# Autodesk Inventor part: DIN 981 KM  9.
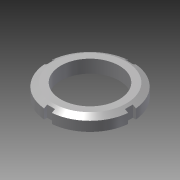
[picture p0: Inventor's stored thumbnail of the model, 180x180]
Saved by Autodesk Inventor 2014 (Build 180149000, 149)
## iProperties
Created: 2001-02
Part Number: DIN 981 KM  9.
Material: Steel, Mild
Description: Locknut KM  9 DIN 981.
Document SubType Name: Modeling
Standard: DIN 981
Density: 7.86 g/cm^3
Appearance: Steel
ProtocolID: P00020917134520337
Protocol: P00020917134520337<@PID>[Version]<@EL>Version=2.2<@EL>[Synchronize]<@EL>ChangedVars=<@EL>[Main]<@EL>View=MODEL<@EL>DataFile=SpiData|D981<@EL>Standard=DIN<@EL>Pa
Control State: 0
Master: False
Checked Out: False
Shininess: 20.0
Length Units: 11269
Angle Units: 11279
Time Units: 11290
Mass Units: 11283
Length Display Precision: 3
Angle Display Precision: 2
BOM1: Locknut
BOM2: KM  9
BOM3: DIN 981
Density: 7.859999999999999
Volumn: 121.29518193394952
Area: 270.0014711948008
PropertySet Name: Model Information
Author: PaulN
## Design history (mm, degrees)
sketch "Sketch2"
  geometry: L1 (22.5, 0)-(22.5, 10); L2 (22.5, 10)-(28, 10); L3 (28, 10)-(32.5, 7.402); L4 (32.5, 7.402)-(32.5, 0); L5 (32.5, 0)-(22.5, 0); L6 (0, 0)-(0, 10); 1 further point
  constraints: 12 end point, 2 parallel, 2 perpendicular, 1 coincident, 1 horizontal alignment, 1 point on line, 1 vertical, 1 other
  dimensions: "d0" = 10 distance between parallel lines of L5 L2 (= prf_B); "d1" = 30 deg angle of L3 L2 (= prf_a); "d2" = 45 diameter of L1 L6 (= prf_d); "d3" = 65 diameter of L4 L6 (= prf_d0); "d4" = 56 diameter of L2.end L6 (= prf_d1)
revolve "Revolution1" sketch "Sketch2" stored, may be unused: angle "d5" = 90 deg
sketch "Sketch3"
  geometry: L1 (3, 32.5)-(-3, 32.5); L2 (-3, 32.5)-(-3, 30); L3 (-3, 30)-(3, 30); L4 (3, 30)-(3, 32.5); L5 (0, -45.5)-(0, 45.5) reference; 2 further points
  constraints: 8 end point, 2 parallel, 1 horizontal, 1 midpoint, 1 perpendicular, 1 point on line, 1 vertical alignment, 1 other
  dimensions: "d6" = 6 distance of L1.start L1.end (= prf_bb); "d7" = 2.5 distance of L1.end L2.end (= prf_h)
extrude "Extrusion1" cut sketch "Sketch3" stored distance "d8" = 10; taper "d9" = 0 deg
pattern_circular "Circular Pattern1" dims angle "d12" = 360 deg
thread "Thread1" dims "d14" = 10, "d15" = 0
body "Solid1"
other parameters: "prf_d" = 45 [user parameter; used in 1 equation term], "prf_d0" = 65 [user parameter; used in 1 equation term], "prf_B" = 10 [user parameter; used in 1 equation term], "prf_a" = 30 deg [user parameter; used in 1 equation term], "prf_d1" = 56 [user parameter; used in 1 equation term], "prf_bb" = 6 [user parameter; used in 1 equation term], "prf_h" = 2.5 [user parameter; used in 1 equation term], "d16" = 0
